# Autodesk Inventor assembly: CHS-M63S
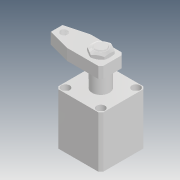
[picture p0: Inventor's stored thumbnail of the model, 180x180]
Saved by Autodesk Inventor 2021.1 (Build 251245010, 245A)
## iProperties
Created: 2019-12
Part Number: CHS-M63S
Description: STEP AP214
Document SubType Name: Assembly
Designer: user
Title: CHS-M63S.STEP
Revision Number: ÈÎºÎ
Sending System: SolidWorks 2016
Preprocessor: SwSTEP 2.0
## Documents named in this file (5)
- D:\Vault_2016\Projekty\Clamptek\Hydraulic\CHS\CHS-63\Inventor\CHS-M63S\CHS-M63S.iam
- D:\Vault_2016\Projekty\Clamptek\Hydraulic\CHS\CHS-63\Inventor\CHS-M63S\CHS-63S-02_2.ipt
- D:\Vault_2016\Projekty\Clamptek\Hydraulic\CHS\CHS-63\Inventor\CHS-M63S\CHS-M63(BT).ipt
- D:\Vault_2016\Projekty\Clamptek\Hydraulic\CHS\CHS-63\Inventor\CHS-M63S\M24_2.ipt
- D:\Vault_2016\Projekty\Clamptek\Hydraulic\CHS\CHS-63\Inventor\CHS-M63S\CHS-63S-01_2.ipt
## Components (4 placed, 4 different names)
1. CHS-63S-02_2_1
2. CHS-M63(BT)_2
3. M24_2_3
4. CHS-63S-01_2_4
